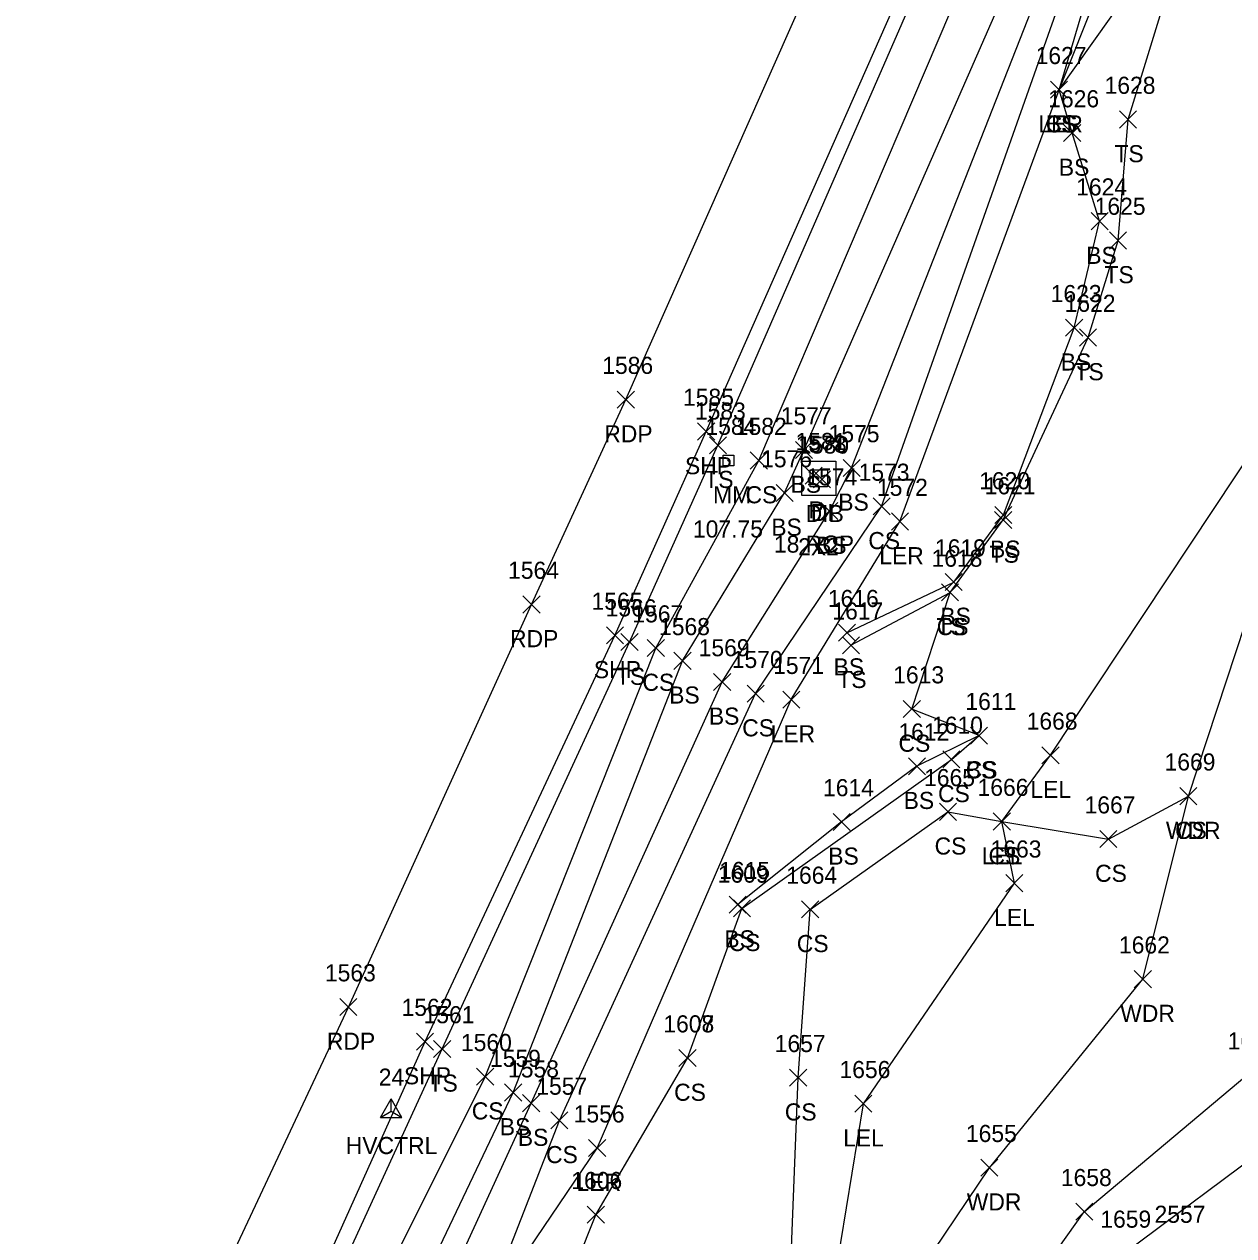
# Model space of a CAD drawing. Extents: x 1483143 to 1488182, y 802902 to 807581.
# Drawn here: x 1487613.3 to 1487754.7, y 805974.5 to 806116.2 of the extents above; entities that cross this region are included whole.
import ezdxf

# ---------------------------------------------------------------- set-up
doc = ezdxf.new("R2010")
doc.units = 0
for name, color, linetype in [('C_A', 7, 'Continuous'), ('C_I', 7, 'Continuous'), ('CPSM', 7, 'Continuous'), ('D_A', 7, 'Continuous'), ('D_C', 7, 'Continuous'), ('D_I', 7, 'Continuous'), ('D_TIC', 7, 'Continuous'), ('DS', 7, 'Continuous'), ('L_A', 7, 'Continuous'), ('L_I', 7, 'Continuous'), ('L_TIC', 7, 'Continuous'), ('LARO', 7, 'Continuous'), ('LAWA', 7, 'Continuous'), ('LELB', 7, 'Continuous'), ('P_A', 7, 'Continuous'), ('P_I', 7, 'Continuous'), ('P_TIC', 7, 'Continuous'), ('PET', 7, 'Continuous'), ('PSP', 7, 'Continuous'), ('S_A', 7, 'Continuous'), ('S_C', 7, 'Continuous'), ('S_I', 7, 'Continuous'), ('SRM', 7, 'Continuous')]:
    doc.layers.add(name, color=color, linetype=linetype)

msp = doc.modelspace()

# ---------------------------------------------------------------- linework, layer by layer
at = {"layer": 'CPSM'}
for p, q in [((1487654.98, 805988.33), (1487656.23, 805990.5)), ((1487657.48, 805988.33), (1487656.23, 805990.5)), ((1487656.23, 805989.05), (1487656.23, 805990.5)), ((1487654.98, 805988.33), (1487656.23, 805989.05)), ((1487656.23, 805989.05), (1487656.23, 805989.05)), ((1487656.23, 805989.05), (1487657.48, 805988.33)), ((1487654.98, 805988.33), (1487657.48, 805988.33))]:
    msp.add_line(p, q, dxfattribs=at)
at = {"layer": 'D_TIC'}
for points in [[(1487704.61, 806062.39), (1487706.61, 806064.39)], [(1487706.61, 806062.39), (1487704.61, 806064.39)], [(1487705.58, 806061.97), (1487707.58, 806063.97)], [(1487707.58, 806061.97), (1487705.58, 806063.97)]]:
    msp.add_lwpolyline(points, dxfattribs=at)
at = {"layer": 'DS'}
for p, q in [((1487704.22, 806065.08), (1487708.22, 806065.08)), ((1487704.22, 806061.08), (1487704.22, 806065.08)), ((1487705.22, 806062.08), (1487705.22, 806064.08)), ((1487705.22, 806064.08), (1487707.22, 806064.08)), ((1487707.22, 806064.08), (1487707.22, 806062.08)), ((1487708.22, 806065.08), (1487708.22, 806061.08)), ((1487706.23, 806063.08), (1487706.23, 806063.08)), ((1487706.23, 806063.08), (1487706.23, 806063.08)), ((1487708.22, 806061.08), (1487704.22, 806061.08)), ((1487707.22, 806062.08), (1487705.22, 806062.08))]:
    msp.add_line(p, q, dxfattribs=at)
at = {"layer": 'L_TIC'}
for points in [[(1487733.3, 806107.53), (1487735.3, 806109.53)], [(1487735.3, 806107.53), (1487733.3, 806109.53)], [(1487733.3, 806107.53), (1487735.3, 806109.53)], [(1487735.3, 806107.53), (1487733.3, 806109.53)], [(1487733.3, 806107.53), (1487735.3, 806109.53)], [(1487735.3, 806107.53), (1487733.3, 806109.53)], [(1487741.36, 806104.05), (1487743.36, 806106.05)], [(1487743.36, 806104.05), (1487741.36, 806106.05)], [(1487734.83, 806102.47), (1487736.83, 806104.47)], [(1487736.83, 806102.47), (1487734.83, 806104.47)], [(1487738.04, 806092.16), (1487740.04, 806094.16)], [(1487740.04, 806092.16), (1487738.04, 806094.16)], [(1487740.2, 806089.9), (1487742.2, 806091.9)], [(1487742.2, 806089.9), (1487740.2, 806091.9)], [(1487735.06, 806079.69), (1487737.06, 806081.69)], [(1487737.06, 806079.69), (1487735.06, 806081.69)], [(1487736.69, 806078.55), (1487738.69, 806080.55)], [(1487738.69, 806078.55), (1487736.69, 806080.55)], [(1487693.42, 806065.95), (1487695.42, 806067.95)], [(1487695.42, 806065.95), (1487693.42, 806067.95)], [(1487703.47, 806065.39), (1487705.47, 806067.39)], [(1487705.47, 806065.39), (1487703.47, 806067.39)], [(1487698.2, 806064.16), (1487700.2, 806066.16)], [(1487700.2, 806064.16), (1487698.2, 806066.16)], [(1487709.05, 806063.3), (1487711.05, 806065.3)], [(1487711.05, 806063.3), (1487709.05, 806065.3)], [(1487701.22, 806060.37), (1487703.22, 806062.37)], [(1487703.22, 806060.37), (1487701.22, 806062.37)], [(1487706.45, 806058.25), (1487708.45, 806060.25)], [(1487708.45, 806058.25), (1487706.45, 806060.25)], [(1487712.56, 806058.8), (1487714.56, 806060.8)], [(1487714.56, 806058.8), (1487712.56, 806060.8)], [(1487726.79, 806057.8), (1487728.79, 806059.8)], [(1487728.79, 806057.8), (1487726.79, 806059.8)], [(1487714.7, 806057.03), (1487716.7, 806059.03)], [(1487716.7, 806057.03), (1487714.7, 806059.03)], [(1487726.77, 806057.21), (1487728.77, 806059.21)], [(1487728.77, 806057.21), (1487726.77, 806059.21)], [(1487720.98, 806049.95), (1487722.98, 806051.95)], [(1487722.98, 806049.95), (1487720.98, 806051.95)], [(1487720.56, 806048.74), (1487722.56, 806050.74)], [(1487722.56, 806048.74), (1487720.56, 806050.74)], [(1487720.56, 806048.74), (1487722.56, 806050.74)], [(1487722.56, 806048.74), (1487720.56, 806050.74)], [(1487708.5, 806044.03), (1487710.5, 806046.03)], [(1487710.5, 806044.03), (1487708.5, 806046.03)], [(1487683.09, 806042.93), (1487685.09, 806044.93)], [(1487685.09, 806042.93), (1487683.09, 806044.93)], [(1487686.16, 806042.23), (1487688.16, 806044.23)], [(1487688.16, 806042.23), (1487686.16, 806044.23)], [(1487708.97, 806042.56), (1487710.97, 806044.56)], [(1487710.97, 806042.56), (1487708.97, 806044.56)], [(1487689.28, 806040.74), (1487691.28, 806042.74)], [(1487691.28, 806040.74), (1487689.28, 806042.74)], [(1487693.92, 806038.27), (1487695.92, 806040.27)], [(1487695.92, 806038.27), (1487693.92, 806040.27)], [(1487697.82, 806036.9), (1487699.82, 806038.9)], [(1487699.82, 806036.9), (1487697.82, 806038.9)], [(1487701.99, 806036.2), (1487703.99, 806038.2)], [(1487703.99, 806036.2), (1487701.99, 806038.2)], [(1487716.09, 806035.1), (1487718.09, 806037.1)], [(1487718.09, 806035.1), (1487716.09, 806037.1)], [(1487723.95, 806031.99), (1487725.95, 806033.99)], [(1487725.95, 806031.99), (1487723.95, 806033.99)], [(1487723.95, 806031.99), (1487725.95, 806033.99)], [(1487725.95, 806031.99), (1487723.95, 806033.99)], [(1487720.71, 806029.21), (1487722.71, 806031.21)], [(1487722.71, 806029.21), (1487720.71, 806031.21)], [(1487732.3, 806029.69), (1487734.3, 806031.69)], [(1487734.3, 806029.69), (1487732.3, 806031.69)], [(1487716.69, 806028.41), (1487718.69, 806030.41)], [(1487718.69, 806028.41), (1487716.69, 806030.41)], [(1487748.42, 806024.91), (1487750.42, 806026.91)], [(1487750.42, 806024.91), (1487748.42, 806026.91)], [(1487748.42, 806024.91), (1487750.42, 806026.91)], [(1487750.42, 806024.91), (1487748.42, 806026.91)], [(1487720.31, 806023.08), (1487722.31, 806025.08)], [(1487722.31, 806023.08), (1487720.31, 806025.08)], [(1487707.88, 806021.9), (1487709.88, 806023.9)], [(1487709.88, 806021.9), (1487707.88, 806023.9)], [(1487726.61, 806021.94), (1487728.61, 806023.94)], [(1487728.61, 806021.94), (1487726.61, 806023.94)], [(1487726.61, 806021.94), (1487728.61, 806023.94)], [(1487728.61, 806021.94), (1487726.61, 806023.94)], [(1487739.06, 806019.89), (1487741.06, 806021.89)], [(1487741.06, 806019.89), (1487739.06, 806021.89)], [(1487728.08, 806014.73), (1487730.08, 806016.73)], [(1487730.08, 806014.73), (1487728.08, 806016.73)], [(1487695.73, 806012.22), (1487697.73, 806014.22)], [(1487697.73, 806012.22), (1487695.73, 806014.22)], [(1487696.23, 806011.79), (1487698.23, 806013.79)], [(1487698.23, 806011.79), (1487696.23, 806013.79)], [(1487704.2, 806011.67), (1487706.2, 806013.67)], [(1487706.2, 806011.67), (1487704.2, 806013.67)], [(1487743.09, 806003.51), (1487745.09, 806005.51)], [(1487745.09, 806003.51), (1487743.09, 806005.51)], [(1487661.18, 805995.35), (1487663.18, 805997.35)], [(1487663.18, 805995.35), (1487661.18, 805997.35)], [(1487689.86, 805994.28), (1487691.86, 805996.28)], [(1487691.86, 805994.28), (1487689.86, 805996.28)], [(1487689.86, 805994.28), (1487691.86, 805996.28)], [(1487691.86, 805994.28), (1487689.86, 805996.28)], [(1487666.21, 805992.1), (1487668.21, 805994.1)], [(1487668.21, 805992.1), (1487666.21, 805994.1)], [(1487702.8, 805991.98), (1487704.8, 805993.98)], [(1487704.8, 805991.98), (1487702.8, 805993.98)], [(1487669.48, 805990.25), (1487671.48, 805992.25)], [(1487671.48, 805990.25), (1487669.48, 805992.25)], [(1487671.59, 805989.01), (1487673.59, 805991.01)], [(1487673.59, 805989.01), (1487671.59, 805991.01)], [(1487710.43, 805988.94), (1487712.43, 805990.94)], [(1487712.43, 805988.94), (1487710.43, 805990.94)], [(1487674.89, 805986.99), (1487676.89, 805988.99)], [(1487676.89, 805986.99), (1487674.89, 805988.99)], [(1487679.31, 805983.75), (1487681.31, 805985.75)], [(1487681.31, 805983.75), (1487679.31, 805985.75)], [(1487725.15, 805981.46), (1487727.15, 805983.46)], [(1487727.15, 805981.46), (1487725.15, 805983.46)], [(1487679.15, 805975.96), (1487681.15, 805977.96)], [(1487681.15, 805975.96), (1487679.15, 805977.96)], [(1487736.25, 805976.31), (1487738.25, 805978.31)], [(1487738.25, 805976.31), (1487736.25, 805978.31)]]:
    msp.add_lwpolyline(points, dxfattribs=at)
at = {"layer": 'LARO'}
for points in [[(1487666.95, 805964.97), (1487680.31, 805984.75), (1487702.99, 806037.2), (1487715.7, 806058.03), (1487734.3, 806108.53), (1487742.02, 806134.63), (1487761.66, 806177.53), (1487786.65, 806227.9), (1487808.03, 806277.33), (1487813.76, 806294.17), (1487828.9, 806329), (1487831.91, 806346.68), (1487843.29, 806372.21), (1487845.69, 806380.48), (1487852.63, 806386.9), (1487863.18, 806416.3)], [(1487707.45, 805965.6), (1487711.43, 805989.94), (1487729.08, 806015.73), (1487727.61, 806022.94), (1487733.3, 806030.69), (1487757.71, 806067.53), (1487771.86, 806089.23), (1487780.18, 806113.12), (1487784.99, 806127.88), (1487795.38, 806142.88), (1487798.38, 806154.92), (1487804.62, 806182.65), (1487809.88, 806200.54), (1487812.82, 806221.22), (1487820.35, 806238.57)]]:
    msp.add_lwpolyline(points, dxfattribs=at)
at = {"layer": 'LAWA'}
msp.add_lwpolyline([(1487715.74, 805966.94), (1487726.15, 805982.46), (1487744.09, 806004.51), (1487749.42, 806025.91), (1487761.62, 806062.94), (1487776.28, 806087.32), (1487789.38, 806109.3), (1487794.61, 806131.39), (1487795.38, 806142.88), (1487801.9, 806153.24), (1487808.85, 806177.73)], dxfattribs=at)
at = {"layer": 'LELB'}
for points in [[(1487406.66, 805485.41), (1487431.45, 805531.24), (1487454.84, 805575.74), (1487473.75, 805612.05), (1487489.43, 805642.37), (1487507.64, 805678.53), (1487524.82, 805711.39), (1487541.86, 805746.09), (1487557.67, 805776.44), (1487575.49, 805812.01), (1487597.52, 805857.93), (1487620.62, 805906.82), (1487641.85, 805951.94), (1487662.18, 805996.35), (1487684.09, 806043.93), (1487694.42, 806066.95), (1487726.58, 806140.7), (1487745.85, 806185.55), (1487769.04, 806237.65), (1487788.58, 806284.85), (1487808.3, 806333.26), (1487827.52, 806379.6), (1487850.09, 806437.73)], [(1487410.04, 805483.24), (1487436.07, 805529.53), (1487459.78, 805575.03), (1487477.42, 805609.67), (1487492.45, 805639.09), (1487509.86, 805677.27), (1487528.68, 805708.85), (1487545.3, 805744.17), (1487561.79, 805774.32), (1487579.7, 805810.21), (1487602.04, 805856.31), (1487624.97, 805905.57), (1487645.72, 805950.02), (1487667.21, 805993.1), (1487687.16, 806043.23), (1487699.2, 806065.16), (1487730.65, 806138.87), (1487749.96, 806183.58), (1487772.93, 806235.17), (1487792.36, 806283.08), (1487812.9, 806331.5), (1487831.61, 806378.23), (1487855.61, 806436.65)], [(1487413.83, 805481.53), (1487440.22, 805526.89), (1487464.36, 805572.85), (1487481.71, 805606.55), (1487496.63, 805636.25), (1487514.9, 805673.97), (1487535.8, 805705.94), (1487549.07, 805741.59), (1487566.17, 805772.22), (1487583.99, 805807.69), (1487605.26, 805855.28), (1487629.33, 805903.01), (1487650.26, 805948.76), (1487670.48, 805991.25), (1487690.28, 806041.74), (1487702.22, 806061.37), (1487704.47, 806066.39), (1487735.28, 806136.71), (1487754, 806182.42), (1487776.55, 806233.47), (1487796.75, 806281.41), (1487816.88, 806330.25), (1487835.19, 806376.59), (1487859.78, 806434.97)], [(1487417, 805480.8), (1487442.28, 805525.8), (1487466.47, 805571.82), (1487483.84, 805604.86), (1487498.25, 805635.76), (1487518.24, 805671.86), (1487538.47, 805704.77), (1487552.2, 805739.67), (1487568.17, 805771.84), (1487585.97, 805806.76), (1487609.39, 805853.47), (1487632.34, 805900.81), (1487653.02, 805947.32), (1487672.59, 805990.01), (1487694.92, 806039.27), (1487707.45, 806059.25), (1487710.05, 806064.3), (1487737.97, 806135.43), (1487757.4, 806181.42), (1487778.76, 806231.94), (1487799.97, 806279.97), (1487818.92, 806329.91), (1487837.5, 806376), (1487863.45, 806433.38)], [(1487539.8, 805706.7), (1487554.99, 805738.51), (1487564.78, 805761.24), (1487572.42, 805770.06), (1487590.42, 805804.18), (1487613.31, 805851.36), (1487639.64, 805896.3), (1487657.07, 805945.9), (1487666.95, 805964.97), (1487675.89, 805987.99), (1487698.82, 806037.9), (1487713.56, 806059.8), (1487740.03, 806134.78), (1487759.8, 806179.98), (1487782.43, 806230.23), (1487804.48, 806278.55), (1487821.45, 806329.34), (1487839.66, 806374.66), (1487865.87, 806433.14)], [(1487734.3, 806108.53), (1487743.5, 806131.6), (1487748.42, 806142.35), (1487768.3, 806173.23), (1487776.95, 806194.07), (1487797.73, 806226.32)], [(1487709.5, 806045.03), (1487721.98, 806050.95), (1487727.79, 806058.8), (1487736.06, 806080.69), (1487739.04, 806093.16), (1487735.83, 806103.47), (1487734.3, 806108.53), (1487746.67, 806125.92), (1487751.73, 806132.48), (1487759.26, 806150.98), (1487768.04, 806168.06), (1487779.72, 806187.39)], [(1487709.97, 806043.56), (1487721.56, 806049.74), (1487727.77, 806058.21), (1487737.69, 806079.55), (1487741.2, 806090.9), (1487742.36, 806105.05), (1487748.14, 806123.84), (1487752.84, 806133.86), (1487761.63, 806152.29), (1487779.72, 806187.39)], [(1487722.85, 805947.47), (1487728.92, 805957.98), (1487741.86, 805972.44), (1487759.45, 805985.51), (1487774.65, 806014.13), (1487785.01, 806040.02), (1487783.16, 806085.43), (1487789.38, 806109.3)], [(1487714.11, 805946.66), (1487721.66, 805955.35), (1487737.25, 805977.31), (1487756.23, 805993.29), (1487766.26, 806020.25), (1487776.49, 806046.35), (1487776.28, 806087.32)], [(1487634.9, 805859.26), (1487653.95, 805884.01), (1487663.76, 805912.85), (1487668.85, 805923.32), (1487668.04, 805936.93), (1487671.41, 805955.04), (1487680.15, 805976.96), (1487690.86, 805995.28), (1487690.86, 805995.28), (1487697.23, 806012.79), (1487721.71, 806030.21), (1487724.95, 806032.99), (1487717.09, 806036.1), (1487721.56, 806049.74)], [(1487724.95, 806032.99), (1487717.69, 806029.41), (1487708.88, 806022.9), (1487696.73, 806013.22)], [(1487632.01, 805808.09), (1487619.24, 805827.81), (1487647.66, 805852.57), (1487664.34, 805862.45), (1487671.06, 805867.81), (1487675.43, 805874.85), (1487684.3, 805891.3), (1487690.96, 805911.62), (1487700.16, 805920.88), (1487706.33, 805937.53), (1487707.55, 805950.23), (1487702.79, 805967.14), (1487703.8, 805992.98), (1487705.2, 806012.67), (1487721.31, 806024.08), (1487727.61, 806022.94), (1487740.06, 806020.89), (1487749.42, 806025.91)]]:
    msp.add_lwpolyline(points, dxfattribs=at)
at = {"layer": 'P_TIC'}
for points in [[(1487682.65, 806071.29), (1487684.65, 806073.29)], [(1487684.65, 806071.29), (1487682.65, 806073.29)], [(1487692.04, 806067.56), (1487694.04, 806069.56)], [(1487694.04, 806067.56), (1487692.04, 806069.56)], [(1487671.63, 806047.33), (1487673.63, 806049.33)], [(1487673.63, 806047.33), (1487671.63, 806049.33)], [(1487681.38, 806043.71), (1487683.38, 806045.71)], [(1487683.38, 806043.71), (1487681.38, 806045.71)], [(1487650.22, 806000.25), (1487652.22, 806002.25)], [(1487652.22, 806000.25), (1487650.22, 806002.25)], [(1487659.18, 805996.21), (1487661.18, 805998.21)], [(1487661.18, 805996.21), (1487659.18, 805998.21)]]:
    msp.add_lwpolyline(points, dxfattribs=at)
at = {"layer": 'PET'}
msp.add_lwpolyline([(1487396.33, 805490.41), (1487421.9, 805537.94), (1487444.13, 805580.16), (1487464.29, 805618.83), (1487479.8, 805648.39), (1487498.08, 805684.27), (1487514.57, 805717.15), (1487530.55, 805749.06), (1487547.16, 805782.47), (1487564.33, 805817.54), (1487585.71, 805863.32), (1487608.89, 805911.38), (1487630.35, 805956.68), (1487651.22, 806001.25), (1487672.63, 806048.33), (1487683.65, 806072.29), (1487715.61, 806144.47), (1487735.35, 806190.47), (1487757.48, 806241.03), (1487777.65, 806289.15), (1487798.25, 806337.46), (1487817.05, 806384.04), (1487839.67, 806441.4)], dxfattribs=at)
at = {"layer": 'PSP'}
msp.add_lwpolyline([(1487405.03, 805486.21), (1487429.8, 805532.42), (1487452.92, 805576.31), (1487472.37, 805613.24), (1487487.86, 805643.29), (1487506.35, 805679.4), (1487523.34, 805712.45), (1487540.38, 805746.64), (1487556.03, 805777.85), (1487573.44, 805813.27), (1487595.34, 805859.04), (1487618.37, 805906.67), (1487640.09, 805952.42), (1487660.18, 805997.21), (1487682.38, 806044.71), (1487693.04, 806068.56), (1487725.12, 806141.19), (1487744.39, 806185.87), (1487766.81, 806238.55), (1487786.8, 806285.64), (1487806.77, 806333.93), (1487825.55, 806380.21), (1487847.81, 806437.56)], dxfattribs=at)
at = {"layer": 'SRM'}
msp.add_lwpolyline([(1487695.03, 806065.79), (1487696.28, 806065.79), (1487696.28, 806064.54), (1487695.03, 806064.54)], close=True, dxfattribs=at)
msp.add_circle((1487695.66, 806065.16), 0.0833, dxfattribs=at)

# ---------------------------------------------------------------- texts
at = {"layer": 'C_A'}
msp.add_text('HVCTRL', height=2, dxfattribs=at).set_placement((1487650.92, 805984.05))
at = {"layer": 'C_I'}
msp.add_text('24', height=2, dxfattribs=at).set_placement((1487654.77, 805992.05))
at = {"layer": 'D_A'}
for s, p in [('DIB', (1487704.68, 806057.97)), ('P', (1487704.99, 806058.39)), ('DI', (1487705.28, 806058.08))]:
    msp.add_text(s, height=2, dxfattribs=at).set_placement(p)
at = {"layer": 'D_C'}
for s, p in [('18 RCP', (1487700.97, 806054.39)), ('2X2', (1487703.8, 806054.08))]:
    msp.add_text(s, height=2, dxfattribs=at).set_placement(p)
at = {"layer": 'D_I'}
for s, p in [('1581', (1487703.48, 806066.39)), ('1578', (1487703.53, 806066.08)), ('1580', (1487703.8, 806065.97))]:
    msp.add_text(s, height=2, dxfattribs=at).set_placement(p)
at = {"layer": 'L_A'}
for s, p in [('LER', (1487731.88, 806103.53)), ('CS', (1487732.74, 806103.53)), ('BS', (1487732.74, 806103.53)), ('TS', (1487740.77, 806100.05)), ('BS', (1487734.27, 806098.47)), ('BS', (1487737.48, 806088.16)), ('TS', (1487739.61, 806085.9)), ('BS', (1487734.5, 806075.69)), ('TS', (1487736.1, 806074.55)), ('TS', (1487692.83, 806061.95)), ('BS', (1487702.91, 806061.39)), ('CS', (1487697.65, 806060.16)), ('BS', (1487708.49, 806059.3)), ('BS', (1487700.66, 806056.37)), ('CS', (1487712, 806054.8)), ('BS', (1487705.89, 806054.25)), ('TS', (1487726.18, 806053.21)), ('BS', (1487726.23, 806053.8)), ('LER', (1487713.28, 806053.03)), ('TS', (1487719.97, 806044.74)), ('CS', (1487720, 806044.74)), ('BS', (1487720.42, 806045.95)), ('BS', (1487707.94, 806040.03)), ('TS', (1487682.5, 806038.93)), ('CS', (1487685.6, 806038.23)), ('TS', (1487708.38, 806038.56)), ('BS', (1487688.72, 806036.74)), ('BS', (1487693.36, 806034.27)), ('CS', (1487697.26, 806032.9)), ('LER', (1487700.58, 806032.2)), ('CS', (1487715.53, 806031.1)), ('CS', (1487723.39, 806027.99)), ('BS', (1487723.39, 806027.99)), ('CS', (1487720.15, 806025.21)), ('LEL', (1487730.94, 806025.69)), ('BS', (1487716.13, 806024.41)), ('WDR', (1487746.79, 806020.91)), ('CS', (1487747.86, 806020.91)), ('BS', (1487707.32, 806017.9)), ('CS', (1487719.75, 806019.08)), ('LEL', (1487725.25, 806017.94)), ('CS', (1487726.05, 806017.94)), ('CS', (1487738.51, 806015.89)), ('LEL', (1487726.71, 806010.73)), ('BS', (1487695.17, 806008.22)), ('CS', (1487695.67, 806007.79)), ('CS', (1487703.64, 806007.67)), ('WDR', (1487741.45, 805999.51)), ('TS', (1487660.59, 805991.35)), ('CS', (1487689.3, 805990.28)), ('CS', (1487689.3, 805990.28)), ('CS', (1487665.65, 805988.1)), ('CS', (1487702.24, 805987.98)), ('BS', (1487668.92, 805986.25)), ('BS', (1487671.03, 805985.01)), ('LEL', (1487709.06, 805984.94)), ('CS', (1487674.33, 805982.99)), ('LER', (1487677.89, 805979.75)), ('WDR', (1487723.51, 805977.46))]:
    msp.add_text(s, height=2, dxfattribs=at).set_placement(p)
at = {"layer": 'L_I'}
for s, p in [('1627', (1487731.56, 806111.53)), ('1627', (1487731.56, 806111.53)), ('1627', (1487731.56, 806111.53)), ('1628', (1487739.62, 806108.05)), ('1626', (1487733.03, 806106.47)), ('1624', (1487736.3, 806096.16)), ('1625', (1487738.46, 806093.9)), ('1623', (1487733.32, 806083.69)), ('1622', (1487734.95, 806082.55)), ('1583', (1487691.73, 806069.95)), ('1577', (1487701.77, 806069.39)), ('1582', (1487696.51, 806068.16)), ('1575', (1487707.36, 806067.3)), ('1576', (1487699.47, 806064.37)), ('1574', (1487704.76, 806062.25)), ('1573', (1487710.87, 806062.8)), ('1620', (1487724.96, 806061.8)), ('1572', (1487713.01, 806061.03)), ('1621', (1487725.6, 806061.21)), ('1619', (1487719.79, 806053.95)), ('1618', (1487719.39, 806052.74)), ('1618', (1487719.39, 806052.74)), ('1616', (1487707.27, 806048.03)), ('1566', (1487681.3, 806046.93)), ('1567', (1487684.42, 806046.23)), ('1617', (1487707.8, 806046.56)), ('1568', (1487687.54, 806044.74)), ('1569', (1487692.17, 806042.27)), ('1570', (1487696.04, 806040.9)), ('1571', (1487700.87, 806040.2)), ('1613', (1487714.91, 806039.1)), ('1611', (1487723.35, 806035.99)), ('1611', (1487723.35, 806035.99)), ('1668', (1487730.51, 806033.69)), ('1612', (1487715.52, 806032.41)), ('1610', (1487719.45, 806033.21)), ('1669', (1487746.63, 806028.91)), ('1669', (1487746.63, 806028.91)), ('1665', (1487718.52, 806027.08)), ('1614', (1487706.71, 806025.9)), ('1666', (1487724.77, 806025.94)), ('1666', (1487724.77, 806025.94)), ('1667', (1487737.28, 806023.89)), ('1663', (1487726.29, 806018.73)), ('1609', (1487694.4, 806015.79)), ('1615', (1487694.56, 806016.22)), ('1664', (1487702.41, 806015.67)), ('1662', (1487741.3, 806007.51)), ('1561', (1487660.01, 805999.35)), ('1607', (1487688.04, 805998.28)), ('1608', (1487688.04, 805998.28)), ('1560', (1487664.38, 805996.1)), ('1657', (1487701.06, 805995.98)), ('1661', (1487754.01, 805996.29)), ('1559', (1487667.78, 805994.25)), ('1558', (1487669.89, 805993.01)), ('1656', (1487708.63, 805992.94)), ('1557', (1487673.19, 805990.99)), ('1556', (1487677.56, 805987.75)), ('1655', (1487723.41, 805985.46)), ('1606', (1487677.28, 805979.96)), ('1658', (1487734.51, 805980.31)), ('1659', (1487739.12, 805975.44)), ('1659', (1487739.12, 805975.44)), ('2557', (1487745.46, 805976.01))]:
    msp.add_text(s, height=2, dxfattribs=at).set_placement(p)
at = {"layer": 'P_A'}
for s, p in [('RDP', (1487681.14, 806067.29)), ('SHP', (1487690.57, 806063.56)), ('RDP', (1487670.12, 806043.33)), ('SHP', (1487679.92, 806039.71)), ('RDP', (1487648.71, 805996.25)), ('SHP', (1487657.72, 805992.21))]:
    msp.add_text(s, height=2, dxfattribs=at).set_placement(p)
at = {"layer": 'P_I'}
for s, p in [('1586', (1487680.9, 806075.29)), ('1585', (1487690.34, 806071.56)), ('1564', (1487669.89, 806051.33)), ('1565', (1487679.64, 806047.71)), ('1563', (1487648.48, 806004.25)), ('1562', (1487657.44, 806000.21))]:
    msp.add_text(s, height=2, dxfattribs=at).set_placement(p)
at = {"layer": 'S_A'}
msp.add_text('MM', height=2, dxfattribs=at).set_placement((1487693.85, 806060.16))
at = {"layer": 'S_C'}
msp.add_text('107.75', height=2, dxfattribs=at).set_placement((1487691.5, 806056.16))
at = {"layer": 'S_I'}
msp.add_text('1584', height=2, dxfattribs=at).set_placement((1487692.96, 806068.16))

doc.saveas('drawing.dxf')
